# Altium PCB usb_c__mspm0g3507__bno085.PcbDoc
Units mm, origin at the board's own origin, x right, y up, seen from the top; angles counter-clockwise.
Board outline 92 x 60 mm, 2 copper layers (Top, Bottom), stack 0 mm thick; 44 components, 36 nets, 224 pads, 88 vias.
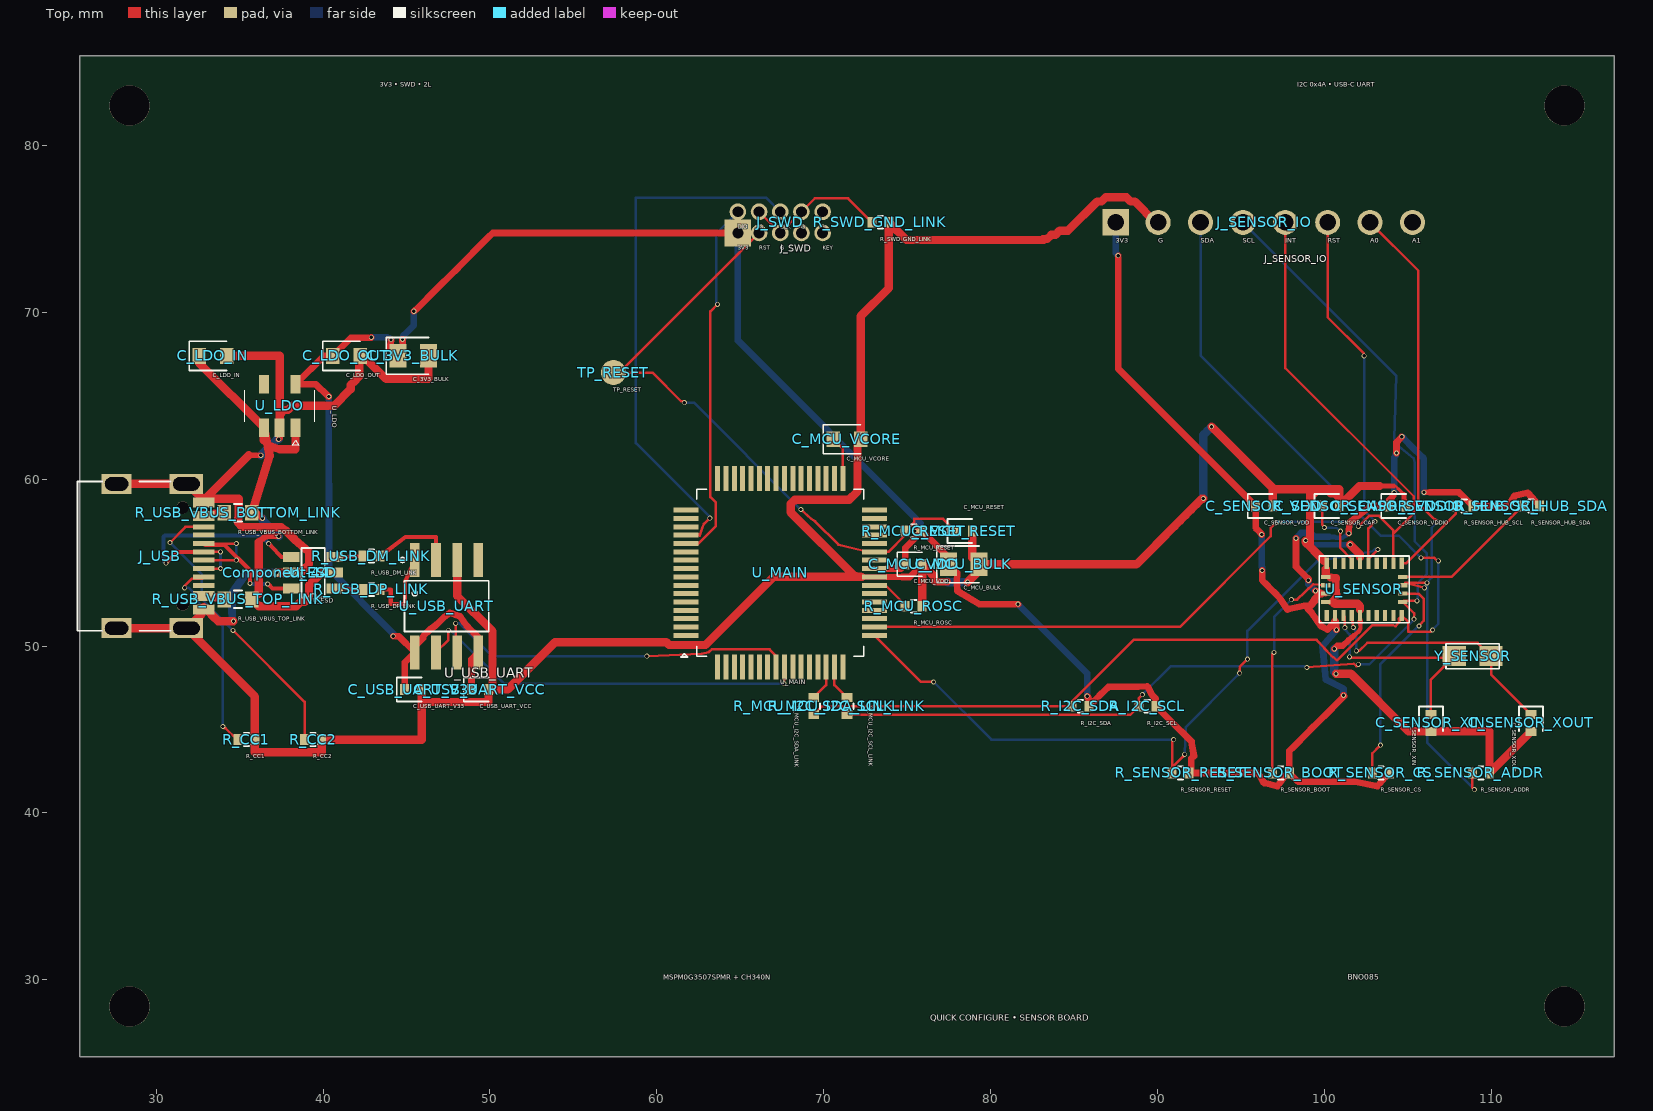
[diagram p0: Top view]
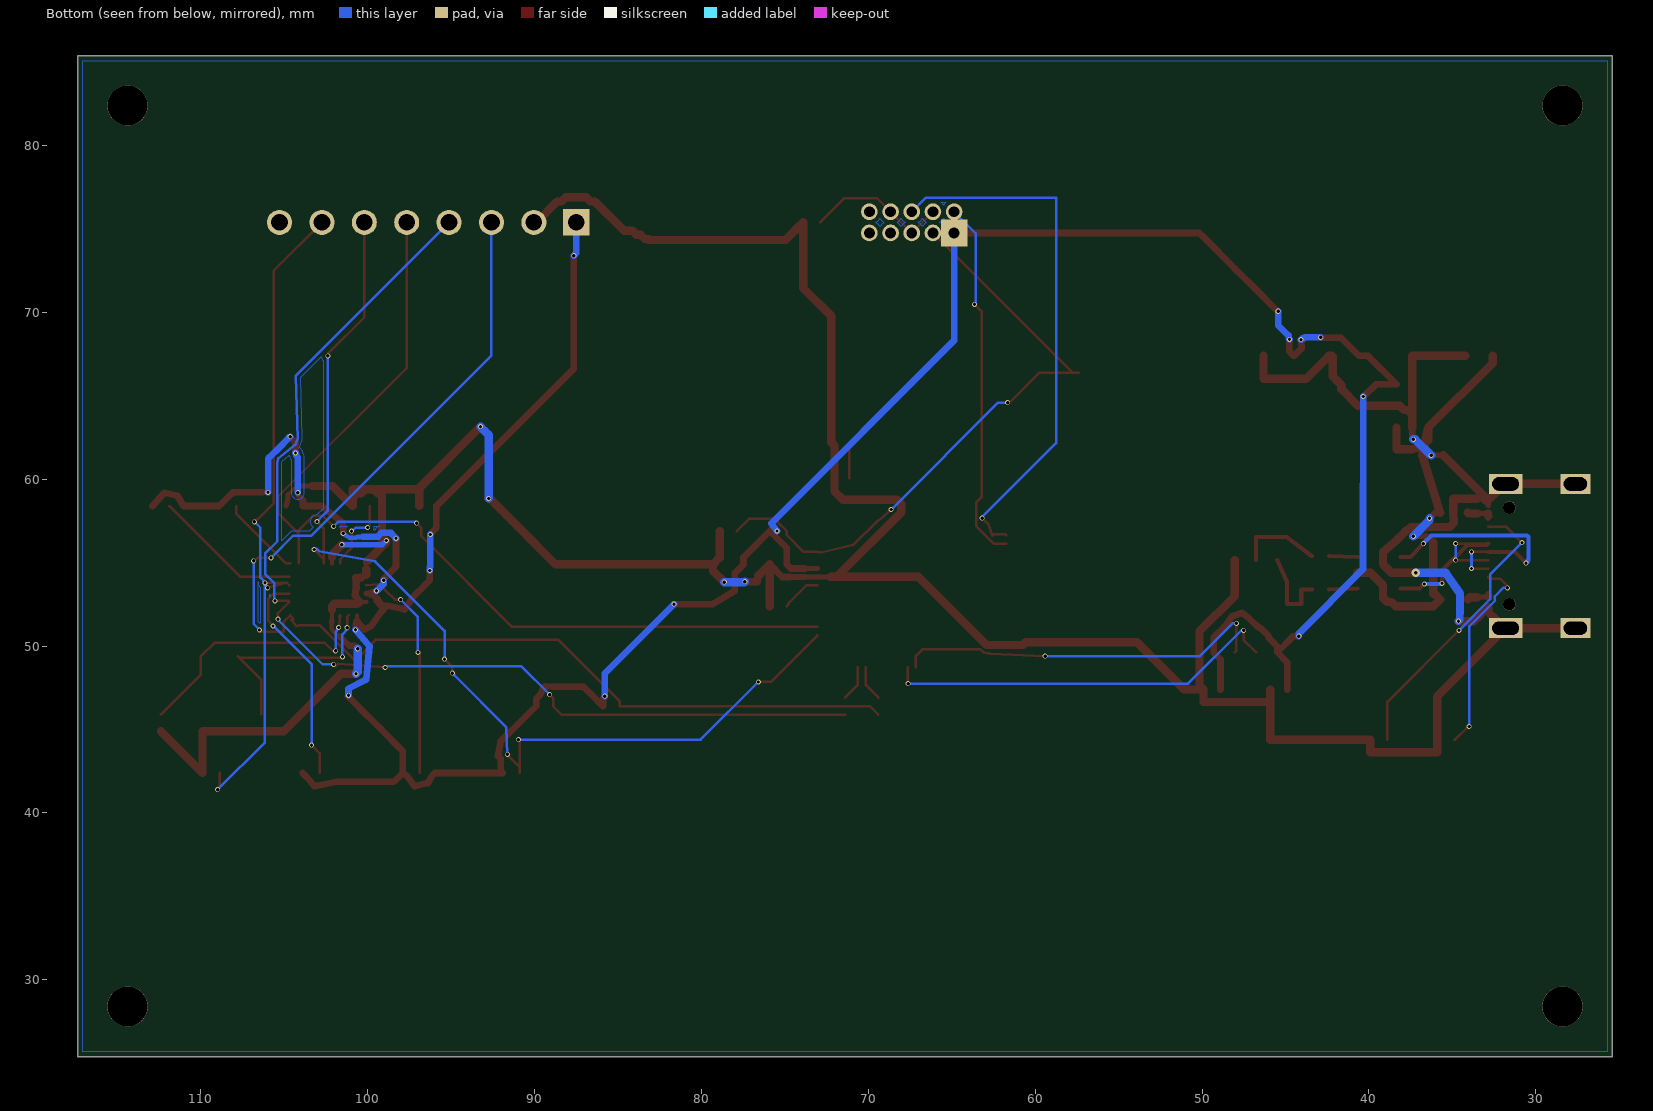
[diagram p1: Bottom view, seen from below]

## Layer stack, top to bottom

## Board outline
25.4,85.4 117.4,85.4 117.4,25.4 25.4,25.4

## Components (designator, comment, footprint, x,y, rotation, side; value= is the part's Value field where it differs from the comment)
C_3V3_BULK "" TSCIRCUIT-2.8500x1.4000mm 45.4,67.4 r0 top
C_LDO_IN "" TSCIRCUIT-2.4500x0.9500mm 33.4,67.4 r0 top
C_LDO_OUT "" TSCIRCUIT-2.4500x0.9500mm 41.4,67.4 r0 top
C_MCU_BULK "" TSCIRCUIT-2.8500x1.4000mm 78.4,54.9 r0 top
C_MCU_RESET "" TSCIRCUIT-1.5600x0.6400mm 78.4,56.9 r0 top
C_MCU_VCORE "" TSCIRCUIT-2.4500x0.9500mm 71.4,62.4 r0 top
C_MCU_VDD "" TSCIRCUIT-1.5600x0.6400mm 75.4,54.9 r0 top
C_SENSOR_CAP "" TSCIRCUIT-1.5600x0.6400mm 100.4,58.4 r0 top
C_SENSOR_VDD "" TSCIRCUIT-1.5600x0.6400mm 96.4,58.4 r0 top
C_SENSOR_VDDIO "" TSCIRCUIT-1.5600x0.6400mm 104.4,58.4 r0 top
C_SENSOR_XIN "" TSCIRCUIT-0.6400x1.5600mm 106.4,45.4 r270 top
C_SENSOR_XOUT "" TSCIRCUIT-0.6400x1.5600mm 112.4,45.4 r270 top
C_USB_UART_V33 "" TSCIRCUIT-1.5600x0.6400mm 45.4,47.4 r0 top
C_USB_UART_VCC "" TSCIRCUIT-1.5600x0.6400mm 49.4,47.4 r0 top
Component-44 "" TSCIRCUIT-0.5000x0.5000mm 37.2,54.4 r0 top
J_SENSOR_IO "" TSCIRCUIT-19.2800x1.5000mm 96.4,75.4 r0 top
J_SWD "" TSCIRCUIT-6.0800x2.2700mm 67.4,75.4 r0 top
J_USB "" TSCIRCUIT-6.7732x9.8502mm 30.113,55.4 r90 top
R_CC1 "" TSCIRCUIT-1.5600x0.6400mm 35.4,44.4 r0 top
R_CC2 "" TSCIRCUIT-1.5600x0.6400mm 39.4,44.4 r0 top
R_I2C_SCL "" TSCIRCUIT-1.5600x0.6400mm 89.4,46.4 r0 top
R_I2C_SDA "" TSCIRCUIT-1.5600x0.6400mm 85.4,46.4 r0 top
R_MCU_I2C_SCL_LINK "" TSCIRCUIT-0.6400x1.5600mm 71.4,46.4 r270 top
R_MCU_I2C_SDA_LINK "" TSCIRCUIT-0.6400x1.5600mm 69.4,46.4 r270 top
R_MCU_RESET "" TSCIRCUIT-1.5600x0.6400mm 75.4,56.9 r0 top
R_MCU_ROSC "" TSCIRCUIT-1.5600x0.6400mm 75.4,52.4 r0 top
R_SENSOR_ADDR "" TSCIRCUIT-1.5600x0.6400mm 109.4,42.4 r0 top
R_SENSOR_BOOT "" TSCIRCUIT-1.5600x0.6400mm 97.4,42.4 r0 top
R_SENSOR_CS "" TSCIRCUIT-1.5600x0.6400mm 103.4,42.4 r0 top
R_SENSOR_HUB_SCL "" TSCIRCUIT-1.5600x0.6400mm 108.4,58.4 r0 top
R_SENSOR_HUB_SDA "" TSCIRCUIT-1.5600x0.6400mm 112.4,58.4 r0 top
R_SENSOR_RESET "" TSCIRCUIT-1.5600x0.6400mm 91.4,42.4 r0 top
R_SWD_GND_LINK "" TSCIRCUIT-1.5600x0.6400mm 73.4,75.4 r0 top
R_USB_DM_LINK "" TSCIRCUIT-1.5600x0.6400mm 42.9,55.4 r0 top
R_USB_DP_LINK "" TSCIRCUIT-1.5600x0.6400mm 42.9,53.4 r0 top
R_USB_VBUS_BOTTOM_LINK "" TSCIRCUIT-2.4500x0.9500mm 34.9,58 r0 top
R_USB_VBUS_TOP_LINK "" TSCIRCUIT-2.4500x0.9500mm 34.9,52.8 r0 top
TP_RESET "" TSCIRCUIT-1.5000x1.5000mm 57.4,66.4 r0 top
U_ESD "" TSCIRCUIT-3.6000x2.5000mm 39.4,54.4 r0 top
U_LDO "" TSCIRCUIT-2.5000x3.7000mm 37.4,64.4 r270 top
U_MAIN "" TSCIRCUIT-12.8000x12.8000mm 67.4,54.4 r0 top
U_SENSOR "" TSCIRCUIT-5.2000x3.8000mm 102.4,53.4 r0 top
U_USB_UART "" TSCIRCUIT-4.3840x7.5712mm 47.4,52.4 r0 top
Y_SENSOR "" TSCIRCUIT-3.6000x1.2000mm 108.9,49.4 r0 top

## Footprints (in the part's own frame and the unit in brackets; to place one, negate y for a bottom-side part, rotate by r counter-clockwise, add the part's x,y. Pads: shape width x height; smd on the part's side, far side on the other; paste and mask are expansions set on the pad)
TSCIRCUIT-0.5000x0.5000mm [mm]
TSCIRCUIT-0.6400x1.5600mm [mm]
  rect 0.54x0.64 smd: 1(-0.51,0) 2(0.51,0)
  silkscreen extent -0.98,-0.72 0.51,0.72
TSCIRCUIT-1.5000x1.5000mm [mm]
  round 1.5 smd: 1(0,0)
TSCIRCUIT-1.5600x0.6400mm [mm]
  rect 0.54x0.64 smd: 1(-0.51,0) 2(0.51,0)
  silkscreen extent -0.98,-0.72 0.51,0.72
TSCIRCUIT-2.4500x0.9500mm [mm]
  rect 0.8x0.95 smd: 1(-0.825,0) 2(0.825,0)
  silkscreen extent -1.42,-0.87 0.82,0.87
TSCIRCUIT-2.5000x3.7000mm [mm]
  rect 1.1x0.6 smd: 1(1.3,0.95) 2(1.3,0) 3(1.3,-0.95) 4(-1.3,-0.95) 5(-1.3,0.95)
  silkscreen extent -0.95,-2.1 2.35,2.1
TSCIRCUIT-2.8500x1.4000mm [mm]
  rect 1.025x1.4 smd: 1(-0.913,0) 2(0.913,0)
  silkscreen extent -1.63,-1.1 0.91,1.1
TSCIRCUIT-3.6000x1.2000mm [mm]
  rect 1.4x1.2 smd: 1(-1.1,0) 2(1.1,0)
  silkscreen extent -1.6,-0.75 1.6,0.75
TSCIRCUIT-3.6000x2.5000mm [mm]
  rect 1x0.6 smd: 1(-1.3,-0.95) 2(-1.3,0) 3(-1.3,0.95) 4(1.3,0.95) 5(1.3,0) 6(1.3,-0.95)
  silkscreen extent -0.7,-1.49 0.7,1.49
TSCIRCUIT-4.3840x7.5712mm [mm]
  rect 0.574x2.036 smd: 1(-1.905,2.768) 2(-0.635,2.768) 3(0.635,2.768) 4(1.905,2.768) 5(1.905,-2.768) 6(0.635,-2.768) 7(-0.635,-2.768) 8(-1.905,-2.768)
  silkscreen extent -2.79,-1.52 2.53,2.92
TSCIRCUIT-5.2000x3.8000mm [mm]
  rect 0.25x0.675 smd: 1(-2.25,-1.562) 6(-2.25,1.563) 7(-1.75,1.563) 8(-1.25,1.563) 9(-0.75,1.563) 10(-0.25,1.563) 11(0.25,1.563) 12(0.75,1.563) 13(1.25,1.563) 14(1.75,1.563) 15(2.25,1.563) 20(2.25,-1.562) 21(1.75,-1.562) 22(1.25,-1.562) 23(0.75,-1.562) 24(0.25,-1.562) 25(-0.25,-1.562) 26(-0.75,-1.562) 27(-1.25,-1.562) 28(-1.75,-1.562)
  rect 0.575x0.25 smd: 2(-2.312,-0.75) 3(-2.312,-0.25) 4(-2.312,0.25) 5(-2.312,0.75) 16(2.312,0.75) 17(2.312,0.25) 18(2.312,-0.25) 19(2.312,-0.75)
  silkscreen extent -2.7,-2 2.7,2
TSCIRCUIT-6.0800x2.2700mm [mm]
  rect 1.6x1.6 hole 0.65: 1(-2.54,-0.635)
  round 1 hole 0.65: 2(-2.54,0.635) 3(-1.27,0.635) 4(0,0.635) 5(1.27,0.635) 6(2.54,0.635) 7(2.54,-0.635) 8(1.27,-0.635) 9(0,-0.635) 10(-1.27,-0.635)
TSCIRCUIT-6.7732x9.8502mm [mm]
  rect 0.3x1.3 smd: 1(-3.35,-2.737) 2(-3.05,-2.737) 3(-2.55,-2.737) 4(-2.25,-2.737) 5(-1.75,-2.737) 6(-1.25,-2.737) 7(-0.75,-2.737) 8(-0.25,-2.737) 9(0.25,-2.737) 10(0.75,-2.737) 11(1.25,-2.737) 12(1.75,-2.737) 13(2.55,-2.737) 14(2.25,-2.737) 15(3.35,-2.737) 16(3.05,-2.737)
  rect 1.2x2 hole 0.8 slot 1.6 at 90 deg: 17(-4.325,-1.693) 18(4.325,-1.693)
  rect 1.2x1.8 hole 0.8 slot 1.4 at 90 deg: 19(4.325,2.487) 20(-4.325,2.487)
  round 0.75 hole 0.75 unplated: NPTH-1(-2.9,-1.468) NPTH-2(2.9,-1.468)
  silkscreen extent -4.47,-0.75 4.47,4.83
TSCIRCUIT-12.8000x12.8000mm [mm]
  rect 1.5x0.3 smd: 1(-5.65,-3.75) 2(-5.65,-3.25) 3(-5.65,-2.75) 4(-5.65,-2.25) 5(-5.65,-1.75) 6(-5.65,-1.25) 7(-5.65,-0.75) 8(-5.65,-0.25) 9(-5.65,0.25) 10(-5.65,0.75) 11(-5.65,1.25) 12(-5.65,1.75) 13(-5.65,2.25) 14(-5.65,2.75) 15(-5.65,3.25) 16(-5.65,3.75) 33(5.65,3.75) 34(5.65,3.25) 35(5.65,2.75) 36(5.65,2.25) 37(5.65,1.75) 38(5.65,1.25) 39(5.65,0.75) 40(5.65,0.25) 41(5.65,-0.25) 42(5.65,-0.75) 43(5.65,-1.25) 44(5.65,-1.75) 45(5.65,-2.25) 46(5.65,-2.75) 47(5.65,-3.25) 48(5.65,-3.75)
  rect 0.3x1.5 smd: 17(-3.75,5.65) 18(-3.25,5.65) 19(-2.75,5.65) 20(-2.25,5.65) 21(-1.75,5.65) 22(-1.25,5.65) 23(-0.75,5.65) 24(-0.25,5.65) 25(0.25,5.65) 26(0.75,5.65) 27(1.25,5.65) 28(1.75,5.65) 29(2.25,5.65) 30(2.75,5.65) 31(3.25,5.65) 32(3.75,5.65) 49(3.75,-5.65) 50(3.25,-5.65) 51(2.75,-5.65) 52(2.25,-5.65) 53(1.75,-5.65) 54(1.25,-5.65) 55(0.75,-5.65) 56(0.25,-5.65) 57(-0.25,-5.65) 58(-0.75,-5.65) 59(-1.25,-5.65) 60(-1.75,-5.65) 61(-2.25,-5.65) 62(-2.75,-5.65) 63(-3.25,-5.65) 64(-3.75,-5.65)
  silkscreen extent -5.95,-5.05 5,5
TSCIRCUIT-19.2800x1.5000mm [mm]
  rect 1.6x1.6 hole 1: 1(-8.89,0)
  round 1.5 hole 1: 2(-6.35,0) 3(-3.81,0) 4(-1.27,0) 5(1.27,0) 6(3.81,0) 7(6.35,0) 8(8.89,0)

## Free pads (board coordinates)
  round 2.4 hole 2.4 unplated: NPTH-3(28.4,28.4) NPTH-4(114.4,28.4) NPTH-5(28.4,82.4) NPTH-6(114.4,82.4)

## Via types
v1: diameter 0.3, hole 0.2, Top to Bottom, 87 vias
v2: diameter 0.5, hole 0.2, Top to Bottom, 1 vias

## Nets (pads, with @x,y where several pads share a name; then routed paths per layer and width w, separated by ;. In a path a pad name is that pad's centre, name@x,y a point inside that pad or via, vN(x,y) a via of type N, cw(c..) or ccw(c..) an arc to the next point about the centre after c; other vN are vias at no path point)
".J_SWD > .pin2 to .U_MAIN > .pin12": J_SWD.2 U_MAIN.12 | length 21.9
  Top w0.15: U_MAIN.12 62.497,56.15 63.541,57.194 63.541,58.602 63.209,58.934 63.209,70.059 v1(63.641,70.491)
  Bottom w0.15: v1(63.641,70.491) 63.572,70.56 63.572,70.569 63.572,74.747 J_SWD.2
".J_SWD > .pin4 to .U_MAIN > .pin13": J_SWD.4 U_MAIN.13 | length 32.2
  Top w0.15: U_MAIN.13 61.82,56.72 62.513,56.72 62.568,56.628 62.763,57.17 62.829,57.322 63.178,57.671 v1(63.183,57.671)
  Bottom w0.15: v1(63.183,57.671) 63.212,57.7 58.746,62.167 58.746,76.869 66.566,76.869 J_SWD.4
".U_MAIN > .pin42 to .R_MCU_ROSC > .pin1": R_MCU_ROSC.1 U_MAIN.42 | length 2.4
  Top w0.15: U_MAIN.42 73.719,53.65 74.769,52.6 74.769,52.521 R_MCU_ROSC.1
".U_SENSOR > .CAP to .C_SENSOR_CAP > .pin1": C_SENSOR_CAP.1 U_SENSOR.9 | length 4.6
  Top w0.15: C_SENSOR_CAP.1 99.89,57.265 99.972,57.184 99.972,57.142 v1(100.006,57.108) ; v1(100.979,56.887) 100.953,55.907 101.65,55.21 U_SENSOR.9
  Bottom w0.15: v1(100.006,57.108) 100.739,57.098 100.933,56.903 100.941,56.903 v1(100.979,56.887)
".U_SENSOR > .SENSOR_HUB_SCL to .R_SENSOR_HUB_SCL > .pin1": R_SENSOR_HUB_SCL.1 U_SENSOR.15 | length 4.9
  Top w0.15: U_SENSOR.15 104.899,54.962 107.89,57.953 R_SENSOR_HUB_SCL.1
".U_SENSOR > .SENSOR_HUB_SDA to .R_SENSOR_HUB_SDA > .pin1": R_SENSOR_HUB_SDA.1 U_SENSOR.16 | length 8.9
  Top w0.15: U_SENSOR.16 107.64,54.15 R_SENSOR_HUB_SDA.1
GND: C_3V3_BULK.2 C_LDO_IN.2 C_LDO_OUT.2 C_MCU_BULK.2 C_MCU_RESET.2 C_MCU_VCORE.2 C_MCU_VDD.2 C_SENSOR_CAP.2 C_SENSOR_VDD.2 C_SENSOR_VDDIO.2 C_SENSOR_XIN.2 C_SENSOR_XOUT.2 C_USB_UART_V33.2 C_USB_UART_VCC.2 J_SENSOR_IO.2 J_USB.1 J_USB.2 J_USB.15 J_USB.16 J_USB.17 J_USB.18 J_USB.19 J_USB.20 R_CC1.2 R_CC2.2 R_MCU_ROSC.2 R_SENSOR_ADDR.2 R_SWD_GND_LINK.2 U_ESD.2 U_LDO.2 U_MAIN.41 U_SENSOR.2 U_SENSOR.5 U_SENSOR.6 U_SENSOR.10 U_SENSOR.25 U_USB_UART.3 | length 259
  Top w0.188: 104.163,59.6 104.279,59.601 104.539,59.35
  Top w0.2: 104.539,59.35 104.782,59.108
  Top w0.25: U_SENSOR.5@100.088,54.275 U_SENSOR.5 U_SENSOR.5@100.375,54.121 ; U_SENSOR.6@100.088,54.625 100.088,54.9 U_SENSOR.6 ; U_SENSOR.2@100.369,52.65 U_SENSOR.2 U_SENSOR.2@100.375,52.618 ; 101.775,50.63 102.087,50.9 102.168,51.048 102.159,51.443 ; U_SENSOR.25@102.15,52.175 U_SENSOR.25 102.158,51.5 ; U_SENSOR.10 102.15,55.056 102.15,55.15 102.15,55.244 102.15,55.3 102.15,55.337 ; U_SENSOR.6 100.025,55.087 U_SENSOR.6
  Top w0.275: J_USB.2 J_USB.1@33.132,52.067 ; J_USB.16 J_USB.15@33.04,58.641 ; 104.782,59.097 104.782,59.108
  Top w0.3: J_USB.1@32.699,51.9 J_USB.1 J_USB.1@32.849,52.2 ; J_USB.15@32.699,58.9 J_USB.15 ; J_USB.16@32.849,58.6 J_USB.15 ; J_USB.15@32.999,58.9 J_USB.15 ; J_USB.15@33.04,58.641 33.231,58.832 33.499,58.832 ; U_MAIN.41@73.8,54.15 73.706,54.15 73.612,54.15 73.519,54.15 73.425,54.15 73.331,54.15 73.237,54.15 73.144,54.15 U_MAIN.41 ; 103.342,59.6 103.752,59.6 104.163,59.6 ; U_MAIN.41 72.627,54.15 72.3,54.15 72.585,54.15 U_MAIN.41
  Top w0.312: U_SENSOR.2@100.369,52.65 100.775,53.056 ; 104.782,59.097 104.782,58.813 C_SENSOR_VDDIO.2
  Top w0.325: J_USB.16 J_USB.16@32.849,58.6 ; 35.535,61.436 35.899,61.436 v1(36.263,61.436) ; U_SENSOR.2@100.375,52.618 100.572,52.595 ; 101.462,50.361 101.775,50.63 ; 102.158,51.5 102.159,51.443
  Top w0.35: v1(37.334,62.399) v1@37.4,62.465
  Top w0.375: U_MAIN.41@73.8,54.15 74.253,54.15 74.707,54.15 ; v1(100.611,49.837) 100.791,50.017 ; 101.108,50.017 101.462,50.361
  Top w0.4: 37.2,54.4 U_ESD.2@37.6,54.4 ; v1@37.4,62.465 37.4,62.6 U_LDO.2 ; 74.707,54.15 75.16,54.15 75.41,54.4 75.66,54.65 C_MCU_VDD.2 ; 100.791,50.017 101.108,50.017
  Top w0.437: 100.705,53.806 100.697,53.525 100.775,53.056
  Top w0.45: 76.599,54.211 76.65,53.869 77.025,53.868 v1(77.4,53.867) ; 100.705,53.806 100.713,54.087
  Top w0.475: 71.655,54.15 72.12,54.15 72.3,54.15 72.205,54.15 ; U_SENSOR.5@100.375,54.121 100.4,54.119 100.713,54.087
  Top w0.5: J_USB.20 J_USB.17 ; J_USB.19 J_USB.18 31.874,59.725 32.474,59.125 32.699,58.9 ; 32.699,51.9 32.474,51.675 31.874,51.075 J_USB.17 ; J_USB.1@32.849,52.2 J_USB.2 ; 32.999,58.9 35.535,61.436 ; J_USB.1@33.132,52.067 33.416,51.783 33.699,51.5 v1(34.631,51.5) ; 33.499,58.832 33.658,58.832 34.086,58.832 34.513,58.832 34.941,58.832 34.939,58.436 34.936,58.041 34.9,57.4 35.15,57.15 35.619,57.144 36.087,57.138 36.556,57.131 37.025,57.125 37.494,57.119 37.73,56.959 38.02,56.669 38.311,56.378 39.15,55.65 39.15,54.9 38.9,54.65 38.65,54.4 37.2,54.4 ; C_LDO_IN.2 37.4,67.4 U_LDO.2 37.4,63.9 37.65,64.15 37.9,64.15 38.15,64.4 40.65,64.4 41.65,65.4 41.65,65.65 41.9,65.9 41.9,65.897 41.839,65.836 42.163,66.176 42.163,66.563 42.163,66.951 42.163,67.338 C_LDO_OUT.2 42.4,67.4 43.775,66.025 46.313,66.025 C_3V3_BULK.2 ; U_USB_UART.3 48.035,53.015 50.15,50.9 50.15,47.65 49.91,47.41 C_USB_UART_VCC.2 ; 71.655,54.15 71.19,54.15 70.725,54.15 70.26,54.15 69.796,54.15 69.331,54.15 68.866,54.15 68.401,54.15 67.936,54.15 67.471,54.15 67.006,54.15 62.923,50.067 60.733,50.067 60.567,50.233 53.9,50.233 51.067,47.4 C_USB_UART_VCC.2 ; 72.205,54.15 71.994,54.15 71.947,54.197 71.853,54.197 68.025,58.025 68.025,58.525 68.275,58.775 71.525,58.775 72.025,59.275 72.025,62.025 72.225,62.225 C_MCU_VCORE.2 72.225,62.892 72.225,63.384 72.225,63.876 72.225,64.368 72.225,64.86 72.225,65.352 72.225,65.844 72.225,66.336 72.225,66.828 72.225,67.32 72.225,67.812 72.225,68.303 72.225,68.795 72.225,69.287 72.225,69.779 73.91,71.464 R_SWD_GND_LINK.2 74.262,75.048 74.613,74.697 74.965,74.345 74.987,74.345 75.47,74.345 75.953,74.345 76.436,74.345 76.919,74.345 77.402,74.345 77.885,74.345 78.368,74.345 78.851,74.345 79.335,74.345 79.818,74.345 80.301,74.345 80.784,74.345 81.267,74.345 81.75,74.345 82.233,74.345 82.716,74.345 83.199,74.345 83.15,74.394 83.15,74.4 83.4,74.4 83.65,74.65 83.9,74.65 84.15,74.9 84.65,74.9 86.4,76.65 86.65,76.65 86.9,76.9 88.15,76.9 88.4,76.65 88.65,76.65 89.9,75.4 J_SENSOR_IO.2 ; R_MCU_ROSC.2 C_MCU_VDD.2 76.254,54.556 76.599,54.211 ; v1(78.637,53.838) 79.313,54.513 C_MCU_BULK.2 ; C_MCU_RESET.2 78.91,55.303 C_MCU_BULK.2 ; v1(92.753,58.848) 92.742,58.837 92.681,58.837 92.353,58.509 92.025,58.181 91.697,57.853 91.369,57.525 91.041,57.197 90.713,56.869 90.385,56.541 90.056,56.212 89.728,55.884 89.4,55.556 89.072,55.228 88.744,54.9 88.248,54.9 87.751,54.9 87.255,54.9 86.758,54.9 86.262,54.9 85.766,54.9 85.269,54.9 84.773,54.9 84.276,54.9 83.78,54.9 83.284,54.9 82.787,54.9 82.291,54.9 81.794,54.9 81.298,54.9 80.802,54.9 80.305,54.9 79.809,54.9 C_MCU_BULK.2 ; v1(93.25,63.155) 96.91,59.495 C_SENSOR_VDD.2 96.91,59.4 100.91,59.4 C_SENSOR_CAP.2 ; v1(98.893,56.332) 98.893,56.219 99.207,55.905 99.522,55.591 99.836,55.277 100.025,55.087 99.15,55.962 99.15,59.15 99.4,59.15 99.65,59.4 100.15,59.4 100.4,59.15 100.65,59.15 100.9,58.9 100.9,58.65 100.91,58.64 C_SENSOR_CAP.2 ; 100.088,54.275 100.088,54.625 ; 100.572,52.595 100.627,52.541 101.056,52.541 102.009,52.541 102.15,52.4 U_SENSOR.25@102.15,52.175 ; v1(100.705,48.345) 101.153,48.345 101.601,48.345 105.056,44.89 C_SENSOR_XIN.2 109.91,44.89 R_SENSOR_ADDR.2 110.087,42.577 C_SENSOR_XOUT.2 ; v1(101.559,56.081) v1@101.639,56.001 ; v1@101.639,56 101.992,55.647 102.058,55.581 102.125,55.514 102.15,55.489 102.15,55.431 102.15,55.337 ; 103.342,59.6 102.931,59.6 102.521,59.6 102.11,59.6 101.81,59.3 101.51,59 101.21,58.7 C_SENSOR_CAP.2 ; J_USB.17 35.91,46.971 R_CC1.2 35.91,43.65 39.91,43.65 R_CC2.2 40.41,44.4 40.91,44.4 45.91,44.4 C_USB_UART_V33.2 45.91,46.65 49.91,46.65 C_USB_UART_VCC.2
  Bottom w0.325: v1(98.893,56.332) 98.909,56.316 99.144,56.081 99.627,56.081 100.11,56.081 100.593,56.081
  Bottom w0.337: 100.593,56.081 101.076,56.081
  Bottom w0.35: 101.076,56.081 v1(101.559,56.081)
  Bottom w0.45: 34.543,51.978 34.543,51.588 v1(34.631,51.5)
  Bottom w0.5: 34.543,51.978 34.543,52.368 34.543,52.759 34.543,53.149 35.4,54.4 36.263,54.4 36.731,54.4 37.2,54.4 ; v1(36.263,61.436) 37.226,62.399 v1(37.334,62.399) ; v1(77.4,53.867) 77.429,53.838 v1(78.637,53.838) ; v1(92.753,58.848) 92.753,59.324 92.753,59.801 92.753,60.277 92.753,60.753 92.753,61.229 92.753,61.706 92.753,62.182 92.753,62.658 92.996,62.901 93.24,63.145 v1(93.25,63.155) ; v1(100.611,49.837) 100.611,49.374 100.611,48.911 100.611,48.448 100.689,48.371 100.689,48.361 v1(100.705,48.345)
MAIN_RESET: C_MCU_RESET.1 J_SWD.10 R_MCU_RESET.1 TP_RESET.1 U_MAIN.38 | length 38.4
  Top w0.15: v1(61.65,64.593) 61.562,64.681 61.452,64.681 59.733,66.4 TP_RESET.1 57.765,66.4 J_SWD.10 ; v1(68.634,58.195) 69.254,57.626 69.493,57.483 70.886,56.087 72.817,55.614 73.014,55.614 U_MAIN.38 73.889,55.65 74.889,56.651 R_MCU_RESET.1@74.889,56.899 ; R_MCU_RESET.1 75.442,57.452 75.442,57.636 77.166,57.628 C_MCU_RESET.1
  Bottom w0.15: v1(61.65,64.593) 62.221,64.593 68.534,58.28 68.541,58.28 v1(68.634,58.195)
MCU_I2C_SCL_LOCAL: R_MCU_I2C_SCL_LINK.1 U_MAIN.50 | length 2.2
  Top w0.15: U_MAIN.50 70.65,47.66 R_MCU_I2C_SCL_LINK.1
MCU_I2C_SDA_LOCAL: R_MCU_I2C_SDA_LINK.1 U_MAIN.51 | length 2.2
  Top w0.15: R_MCU_I2C_SDA_LINK.1 70.15,47.66 U_MAIN.51
MSPM0_VCORE: C_MCU_VCORE.1 U_MAIN.32 | length 2.6
  Top w0.15: C_MCU_VCORE.1 71.15,61.825 U_MAIN.32
SENSOR_ADDR0: J_SENSOR_IO.7 R_SENSOR_ADDR.1 U_SENSOR.17 | length 41.4
  Top w0.15: J_SENSOR_IO.7 105.651,72.499 105.645,58.602 105.651,58.558 106.614,57.595 106.661,57.595 v1(106.8,57.456) ; v1(106,53.5) 104.861,53.798 ; v1(106.164,53.798) 104.861,53.798 ; R_SENSOR_ADDR.1 108.89,41.517 108.973,41.434 108.973,41.427 v1(109,41.4) ; 104.861,53.798 U_SENSOR.17 104.861,53.798
  Bottom w0.15: v1(106,53.5) 106.171,53.792 106.168,53.571 106.169,44.229 v1(109,41.4) ; v1(106.164,53.798) 106.264,53.899 106.264,53.931 106.44,54.107 106.44,57.096 v1(106.8,57.456)
SENSOR_ADDR1: J_SENSOR_IO.8
SENSOR_BOOT: R_SENSOR_BOOT.1 U_SENSOR.4 | length 13.3
  Top w0.15: R_SENSOR_BOOT.1 96.89,49.521 96.968,49.599 v1(96.997,49.628) ; v1(98.031,52.785) 98.376,52.785 99.356,53.713 U_SENSOR.4
  Bottom w0.15: v1(96.997,49.628) 96.997,51.751 97.969,52.723 v1(98.031,52.785)
SENSOR_CS: R_SENSOR_CS.1 U_SENSOR.18 | length 13.1
  Top w0.15: R_SENSOR_CS.1 102.89,43.58 103.293,43.983 103.296,43.983 v1(103.374,44.061) ; U_SENSOR.18 105.665,53.15 105.962,52.853 105.962,51.518 v1(105.686,51.206)
  Bottom w0.15: v1(103.374,44.061) 103.374,48.918 105.591,51.136 105.591,51.147 v1(105.686,51.206)
SENSOR_INT: J_SENSOR_IO.5 U_MAIN.47 U_SENSOR.14 | length 60.9
  Top w0.15: U_MAIN.47 91.356,51.15 96.796,56.59 96.796,57.092 96.971,57.267 ; 96.972,57.267 v1(97.078,57.373) ; J_SENSOR_IO.5 97.67,66.671 105.37,58.986 105.37,57.945 104.996,57.586 104.15,56.74 U_SENSOR.14 104.15,56.944 103.291,57.803 102.675,57.803 v1(102.053,57.179)
  Bottom w0.15: v1(97.078,57.373) 97.17,57.465 101.537,57.465 101.767,57.465 v1(102.053,57.179)
SENSOR_RESET: J_SENSOR_IO.6 R_SENSOR_RESET.1 U_MAIN.48 U_SENSOR.11 | length 65.4
  Top w0.15: U_MAIN.48 75.848,47.852 v1(76.597,47.852) ; v1(90.98,44.4) 90.98,44.362 90.89,44.272 R_SENSOR_RESET.1 90.89,42.72 91.548,43.378 v1(91.64,43.52) ; v1(94.931,48.384) 94.931,48.748 95.378,49.195 v1(95.404,49.221) ; J_SENSOR_IO.6 100.21,69.715 102.377,67.548 102.377,67.417 v1(102.397,67.397) ; v1(103.049,57.461) 102.65,57.062 U_SENSOR.11 102.65,55.229 v1(103.216,55.795)
  Bottom w0.15: v1(76.597,47.852) 76.643,47.806 80.049,44.4 v1(90.98,44.4) ; v1(91.64,43.52) 91.69,45.135 94.79,48.235 94.79,48.243 v1(94.931,48.384) ; v1(95.404,49.221) 95.404,50.917 99.563,55.076 102.917,55.7 103.065,55.848 103.163,55.848 v1(103.216,55.795) ; v1(102.397,67.397) 102.397,58.125 102.911,57.611 102.911,57.599 v1(103.049,57.461)
SENSOR_SCL: J_SENSOR_IO.4 R_I2C_SCL.1 R_MCU_I2C_SCL_LINK.2 U_SENSOR.19 | length 66.5
  Top w0.15: R_MCU_I2C_SCL_LINK.2 88.38,45.89 R_I2C_SCL.1 88.89,46.887 89.075,47.072 v1(89.098,47.096) ; v1(98.959,48.722) 101.775,48.948 101.922,48.807 101.945,48.807 v1(102.053,48.915) ; v1(105.384,51.622) 105.4,51.962 U_SENSOR.19 104.779,52.716 v1(105.566,52.716)
  Bottom w0.15: v1(89.098,47.096) 90.808,48.805 98.876,48.805 v1(98.959,48.722) ; J_SENSOR_IO.4 104.312,66.218 104.205,62.442 104.312,62.112 105.375,61.25 105.432,60.992 105.432,56.277 106.162,55.546 106.162,54.331 105.609,53.777 105.609,52.779 105.609,52.759 v1(105.566,52.716) ; v1(102.053,48.915) 102.715,48.915 105.291,51.491 v1(105.384,51.622)
SENSOR_SDA: J_SENSOR_IO.3 R_I2C_SDA.1 R_MCU_I2C_SDA_LINK.2 U_SENSOR.20 | length 73.5
  Top w0.15: R_MCU_I2C_SDA_LINK.2 69.91,46.4 R_I2C_SDA.1 84.89,46.689 88.575,50.374 99.545,50.374 100.425,49.438 100.774,49.145 102.888,51.259 104.146,51.259 104.264,51.183 104.581,51.577 104.465,51.597 104.465,51.645 U_SENSOR.20 105.051,51.436 105.051,50.865 106.399,50.866 v1(106.508,50.972) ; v1(105.801,55.289) 106.603,55.289 106.742,55.15 106.814,55.15 v1(106.847,55.117)
  Bottom w0.15: J_SENSOR_IO.3 92.59,67.422 103.389,56.623 104.47,56.623 105.756,55.337 105.756,55.334 v1(105.801,55.289) ; v1(106.508,50.972) 106.516,50.984 106.516,51.011 106.847,51.342 v1(106.847,55.117)
SENSOR_XIN: C_SENSOR_XIN.1 U_SENSOR.27 Y_SENSOR.1 | length 13
  Top w0.15: U_SENSOR.27 101.226,51.761 v1(101.237,51.107) ; v1(101.52,49.355) 101.558,49.317 101.585,49.317 107.717,49.317 Y_SENSOR.1 106.4,48 C_SENSOR_XIN.1
  Bottom w0.15: v1(101.237,51.107) 101.243,51.071 101.243,50.987 101.52,50.71 v1(101.52,49.355)
SENSOR_XOUT: C_SENSOR_XOUT.1 U_SENSOR.26 Y_SENSOR.2 | length 15.4
  Top w0.15: U_SENSOR.26 101.705,51.782 101.662,51.8 v1(101.752,51.117) ; v1(101.931,49.716) 101.933,49.714 102.098,49.714 102.583,50.199 102.647,50.199 109.201,50.199 Y_SENSOR.2 110,48.31 C_SENSOR_XOUT.1
  Bottom w0.15: v1(101.752,51.117) 101.859,50.94 101.859,50.935 101.931,50.863 v1(101.931,49.716)
swd-ground-1-to-2: J_SWD.3 J_SWD.5 J_SWD.9 R_SWD_GND_LINK.1 | length 8.8
  Top w0.15: J_SWD.3 J_SWD.9 J_SWD.5 69.481,76.846 71.471,76.846 71.471,76.819 R_SWD_GND_LINK.1
UART_MSP_RX: U_MAIN.57 U_USB_UART.6 | length 22.7
  Top w0.15: v1(47.946,51.37) 47.946,49.721 U_USB_UART.6 ; v1(59.4,49.4) 59.432,49.4 62.701,49.544 63.1,49.635 63.3,49.801 66.767,49.802 67.151,49.417 U_MAIN.57
  Bottom w0.15: v1(47.946,51.37) 47.952,51.376 48.148,51.376 50.124,49.4 v1(59.4,49.4)
UART_MSP_TX: U_MAIN.56 U_USB_UART.7 | length 24.1
  Top w0.15: U_USB_UART.7 47.507,50.374 v1(47.507,50.948) ; v1(67.611,47.75) 67.621,47.76 67.621,47.762 67.65,47.792 U_MAIN.56
  Bottom w0.15: v1(47.507,50.948) 47.526,50.967 47.621,50.967 50.839,47.75 v1(67.611,47.75)
usb-dm-device: R_USB_DM_LINK.1 U_ESD.4 | length 1.7
  Top w0.25: U_ESD.4 R_USB_DM_LINK.1
usb-dm-port-tie: J_USB.7 J_USB.9 U_ESD.3 | length 15.4
  Top w0.15: J_USB.7 v1(33.85,54.65) ; J_USB.9 v1(33.85,55.65)
  Top w0.25: v1(30.582,54.978) 31.254,55.65 J_USB.9 ; v1(36.741,56.142) 36.868,56.015 36.868,55.996 37.514,55.35 U_ESD.3
  Bottom w0.15: v1(33.85,54.65) v1(33.85,55.65)
  Bottom w0.25: v1(30.582,54.978) 30.477,55.083 30.477,55.132 30.444,55.165 30.438,55.368 30.429,56.554 30.514,56.624 36.259,56.624 v1(36.741,56.142)
usb-dm-uart: R_USB_DM_LINK.2 U_USB_UART.2 | length 5.1
  Top w0.25: R_USB_DM_LINK.2 44.95,56.55 46.765,56.55 U_USB_UART.2
usb-dp-device: R_USB_DP_LINK.1 U_ESD.6 | length 1.7
  Top w0.25: U_ESD.6 R_USB_DP_LINK.1
usb-dp-port-tie: J_USB.8 J_USB.10 U_ESD.1 | length 11.7
  Top w0.15: J_USB.8 v1(34.8,55.15) ; J_USB.10 v1(34.8,56.15)
  Top w0.25: J_USB.10 32.931,56.068 34.097,56.068 35.631,54.534 v1(35.621,53.765) ; v1(36.679,53.724) 36.687,53.716 36.71,53.716 36.976,53.45 U_ESD.1
  Bottom w0.15: v1(34.8,55.15) v1(34.8,56.15)
  Bottom w0.25: v1(35.621,53.765) 35.665,53.742 35.688,53.742 35.706,53.724 v1(36.679,53.724)
usb-dp-uart: R_USB_DP_LINK.2 U_USB_UART.1 | length 5.1
  Top w0.25: R_USB_DP_LINK.2 44.05,53.4 44.05,52.53 44.9,52.53 44.9,53.85 U_USB_UART.1
USB_CC1: J_USB.6 R_CC1.1 | length 12.1
  Top w0.15: v1(31.698,53.499) 31.698,53.616 32.135,54.053 32.752,54.053 J_USB.6 ; v1(33.986,45.184) 34.102,45.068 34.167,45.068 34.835,44.4 R_CC1.1
  Bottom w0.15: v1(31.698,53.499) 31.704,53.505 31.935,53.505 32.45,52.991 32.45,52.722 33.986,51.186 v1(33.986,45.184)
USB_CC2: J_USB.12 R_CC2.1 | length 17.6
  Top w0.15: v1(30.822,56.2) 31.75,57.15 J_USB.12 ; v1(34.603,50.946) 34.657,50.892 38.89,46.659 R_CC2.1
  Bottom w0.15: v1(30.822,56.2) 30.847,56.153 30.885,56.153 32.739,54.3 32.739,54.172 32.739,52.81 v1(34.603,50.946)
USB_VBUS_BOTTOM_LOCAL: J_USB.13 J_USB.14 R_USB_VBUS_BOTTOM_LINK.1 | length 1.5
  Top w0.3: J_USB.14 J_USB.14@32.849,57.8 ; J_USB.13 32.927,57.95 33.005,57.95 33.083,57.95 33.161,57.95 33.239,57.95 33.317,57.95 33.394,57.95 33.472,57.95 33.499,57.95
  Top w0.475: J_USB.13@32.849,57.8 J_USB.13 ; 33.499,57.95 R_USB_VBUS_BOTTOM_LINK.1@33.762,57.95
  Top w0.5: R_USB_VBUS_BOTTOM_LINK.1@33.762,57.95 34.025,57.95 R_USB_VBUS_BOTTOM_LINK.1
USB_VBUS_TOP_LOCAL: J_USB.3 J_USB.4 R_USB_VBUS_TOP_LINK.1 | length 1.6
  Top w0.3: J_USB.4 32.849,53 J_USB.3 32.944,52.958 33.032,52.939 33.499,52.939
  Top w0.5: 33.499,52.939 33.675,52.939 33.936,52.939 R_USB_VBUS_TOP_LINK.1
VBUS5: C_LDO_IN.1 R_USB_VBUS_BOTTOM_LINK.2 R_USB_VBUS_TOP_LINK.2 U_ESD.5 U_LDO.1 U_LDO.3 | length 29.2
  Top w0.325: v1@36.341,57.68 v1(36.364,57.657)
  Top w0.35: 36.582,56.587 36.958,56.587 v1(37.333,56.587)
  Top w0.375: R_USB_VBUS_BOTTOM_LINK.2 36.021,58 v1@36.341,57.68 ; 36.15,56.246 36.272,56.369 36.582,56.587
  Top w0.5: C_LDO_IN.1 32.575,66.975 U_LDO.3 ; R_USB_VBUS_BOTTOM_LINK.2 36.8,61.4 U_LDO.3 ; 36.15,56.246 36.15,53.15 36.075,53.15 R_USB_VBUS_TOP_LINK.2 35.981,52.544 35.9,52.625 35.9,52.65 36.15,52.4 38.4,52.4 38.65,52.65 38.9,52.65 39.15,52.9 39.15,53.65 39.9,54.4 U_ESD.5 ; U_LDO.1 38.35,61.8 37.4,61.8 36.8,62 36.45,62.35 U_LDO.3
  Bottom w0.5: v1(36.364,57.657) 36.364,57.556 v1(37.333,56.587)
VCC_3V3: C_3V3_BULK.1 C_LDO_OUT.1 C_MCU_BULK.1 C_MCU_VDD.1 C_SENSOR_VDD.1 C_SENSOR_VDDIO.1 C_USB_UART_V33.1 C_USB_UART_VCC.1 J_SENSOR_IO.1 J_SWD.1 R_I2C_SCL.2 R_I2C_SDA.2 R_MCU_RESET.2 R_SENSOR_BOOT.2 R_SENSOR_CS.2 R_SENSOR_HUB_SCL.2 R_SENSOR_HUB_SDA.2 R_SENSOR_RESET.2 U_LDO.5 U_MAIN.40 U_SENSOR.3 U_SENSOR.28 U_USB_UART.5 U_USB_UART.8 | length 205.1
  Top w0.25: U_SENSOR.3@99.851,53.124 100.062,53.124 U_SENSOR.3 ; 100.611,51.5 U_SENSOR.28 100.685,51.5
  Top w0.3: U_MAIN.40 73.15,54.65 73.25,54.65 73.35,54.65 73.45,54.65 73.55,54.65 73.65,54.65 73.75,54.65 U_MAIN.40@73.8,54.65 ; 104.187,59.027 104.187,59.187 v1(104.199,59.199)
  Top w0.325: 104.038,58.879 104.187,59.027 ; v1(105.985,59.219) 106.336,59.219
  Top w0.345: U_SENSOR.3@99.8,53.2 U_SENSOR.3 U_SENSOR.3@99.8,53.2
  Top w0.4: v1(40.348,64.966) 40.311,64.974 40.292,64.983 39.552,65.7 U_LDO.5 40.05,67.4 C_LDO_OUT.1 41.663,68.488 42.876,68.5 v1(42.889,68.512) ; v1(44.072,68.366) 44.017,67.871 C_3V3_BULK.1 44.634,67.546 44.781,67.693 44.768,68.039 v1(44.755,68.386) ; v1(44.2,50.6) 44.527,50.6 U_USB_UART.8 ; C_USB_UART_V33.1 44.89,49.027 U_USB_UART.8 ; v1(45.438,70.073) 45.494,70.129 45.53,70.129 45.803,70.402 46.076,70.675 46.348,70.947 46.621,71.22 46.894,71.493 47.166,71.765 47.439,72.038 47.712,72.311 47.984,72.584 48.257,72.856 48.53,73.129 48.802,73.402 49.075,73.674 49.348,73.947 49.621,74.22 49.893,74.492 50.166,74.765 50.563,74.765 50.96,74.765 51.357,74.765 51.754,74.765 52.152,74.765 52.549,74.765 52.946,74.765 53.343,74.765 53.74,74.765 54.137,74.765 54.534,74.765 54.932,74.765 55.329,74.765 55.726,74.765 56.123,74.765 56.52,74.765 56.917,74.765 57.314,74.765 57.712,74.765 58.109,74.765 58.506,74.765 58.903,74.765 59.3,74.765 59.697,74.765 60.094,74.765 60.491,74.765 60.889,74.765 61.286,74.765 61.683,74.765 62.08,74.765 62.477,74.765 62.874,74.765 63.271,74.765 63.669,74.765 64.066,74.765 64.463,74.765 J_SWD.1 ; C_USB_UART_VCC.1 48.89,49.217 U_USB_UART.5 49.305,49.93 49.305,50.228 49.305,50.526 49.078,50.753 48.851,50.98 48.623,51.207 48.2,51.8 47.6,52 47.242,51.735 46.992,51.486 46.743,51.236 46.4,51 46,50.6 45.994,50.488 45.745,50.238 45.495,49.989 U_USB_UART.8 ; U_MAIN.40@73.8,54.65 73.85,54.65 74.64,54.65 C_MCU_VDD.1 74.89,55.88 R_MCU_RESET.2 ; v1(75.475,56.9) 75.822,56.988 R_MCU_RESET.2 ; v1(81.652,52.517) 79.338,52.508 78.022,53.305 77.972,53.836 78,54.388 C_MCU_BULK.1 77.488,55.323 R_MCU_RESET.2 ; v1(85.8,47) 85.85,46.95 85.85,46.875 85.91,46.815 R_I2C_SDA.2 86.141,46.631 86.372,46.862 86.603,47.093 86.834,47.324 87.065,47.555 87.421,47.558 87.776,47.561 88.131,47.563 88.487,47.566 88.842,47.569 89.4,47.6 89.676,47.079 89.916,46.832 89.913,46.616 R_I2C_SCL.2 90.177,46.137 90.444,45.873 90.711,45.61 90.977,45.346 91.244,45.083 91.511,44.819 91.778,44.556 92.045,44.292 92.2,43.4 92.042,43.28 92.041,42.942 92.041,42.605 92.018,42.508 R_SENSOR_RESET.2 92.281,42.4 92.652,42.4 93.023,42.4 93.394,42.4 93.765,42.4 94.136,42.4 94.507,42.4 94.877,42.4 95.248,42.4 95.619,42.4 95.99,42.4 96.141,42.248 96.4,41.8 97.2,41.6 97.655,42.24 R_SENSOR_BOOT.2 ; v1(87.649,73.403) 87.649,66.641 C_SENSOR_VDD.1 95.89,58.073 95.89,57.746 95.89,57.419 95.89,57.093 96.046,56.936 96.203,56.78 96.203,56.746 v1(96.252,56.697) ; v1(96.288,54.533) 96.288,54.238 96.288,53.943 96.542,53.689 96.797,53.434 97.051,53.18 97.305,52.926 97.8,52.2 98.812,52.417 99.144,52.417 99.4,52.8 ; v1(98.313,56.46) 98.313,56.122 98.313,55.783 98.313,55.445 98.313,55.106 98.313,54.768 98.562,54.519 98.81,54.27 99.059,54.022 99.059,53.952 v1(99.051,53.944) ; v1(99.483,53.313) U_SENSOR.3@99.8,53.2 ; U_SENSOR.3@99.851,53.124 U_SENSOR.3@99.8,53.2 ; 100.611,51.5 100.6,51.4 100.2,51 99.8,51.2 99.261,51.997 99.01,52.248 99.235,52.475 99.461,52.702 99.4,52.8 ; 100.685,51.5 v1(100.739,50.976) ; v1(101.155,47.05) 101.2,47.005 100.926,46.731 100.652,46.457 100.378,46.182 100.103,45.908 99.829,45.634 99.555,45.36 99.281,45.086 99.007,44.812 98.733,44.537 98.458,44.263 98.184,43.989 97.91,43.715 97.91,43.386 97.91,43.057 97.91,42.729 R_SENSOR_BOOT.2 ; v1(101.478,56.759) 101.5,57.4 102.794,58.4 103.16,58.4 103.525,58.4 C_SENSOR_VDDIO.1 103.89,58.73 104.038,58.879 ; R_SENSOR_CS.2 103.645,42.135 103.2,41.6 101.86,41.87 101.48,41.87 101.1,41.87 100.72,41.87 100.34,41.87 99.96,41.87 99.58,41.87 99.2,41.87 98.82,41.87 98.44,41.87 98.175,42.135 R_SENSOR_BOOT.2 ; v1(104.335,61.578) 104.335,61.896 104.335,62.214 104.591,62.47 104.591,62.494 v1(104.655,62.558) ; 106.336,59.219 106.687,59.219 107.038,59.219 107.389,59.219 107.74,59.219 108.091,59.219 108.364,58.946 108.637,58.673 R_SENSOR_HUB_SCL.2 109.265,58.4 109.62,58.4 109.975,58.4 110.33,58.4 110.685,58.4 111.04,58.4 111.4,59 112.2,59.2 R_SENSOR_HUB_SDA.2 ; 99.4,52.8 U_SENSOR.3@99.8,53.2 ; 99.4,52.8 U_SENSOR.3@99.8,53.2
  Bottom w0.262: 100.632,56.551 100.7,56.5 101.1,56.5
  Bottom w0.275: 101.1,56.5 101.289,56.629 v1(101.478,56.759)
  Bottom w0.3: 100.309,56.553 100.632,56.551
  Bottom w0.4: v1(40.348,64.966) 40.351,54.615 44.2,50.766 v1(44.2,50.6) ; v1(42.889,68.512) 43.839,68.501 43.882,68.458 43.979,68.458 v1(44.072,68.366) ; v1(44.755,68.386) 44.795,68.425 44.795,68.59 45.009,68.805 45.224,69.019 45.438,69.233 45.438,69.513 45.438,69.793 v1(45.438,70.073) ; J_SWD.1 64.86,68.322 75.822,57.361 v1(75.475,56.9) ; v1(81.652,52.517) 81.656,52.513 85.8,48.369 v1(85.8,47) ; J_SENSOR_IO.1 87.51,73.547 87.614,73.443 87.614,73.438 v1(87.649,73.403) ; v1(96.252,56.697) 96.252,56.308 96.252,55.919 96.252,55.53 96.252,55.14 96.252,54.751 96.29,54.714 v1(96.288,54.533) v1(96.288,54.533) ; v1(98.313,56.46) 98.471,56.618 98.634,56.781 98.6,56.8 99.2,56.8 99.371,56.561 99.684,56.558 99.997,56.556 100.309,56.553 ; v1(99.051,53.944) 99.051,53.719 99.234,53.536 99.418,53.352 99.45,53.352 v1(99.483,53.313) ; v1(100.739,50.976) 99.9,50 100.1,48 101.155,47.449 v1(101.155,47.05) ; v1(104.199,59.199) 104.199,59.554 104.199,59.909 104.2,60.264 104.2,60.619 104.2,60.974 104.2,61.329 104.285,61.414 104.285,61.528 v1(104.335,61.578) ; v1(104.655,62.558) 104.919,62.294 105.182,62.031 105.446,61.767 105.71,61.503 105.973,61.24 105.973,60.863 105.973,60.487 105.973,60.11 105.973,59.734 105.973,59.357 105.973,59.225 v1(105.985,59.219)
pads on no net: J_SWD.6 J_SWD.7 J_SWD.8 J_USB.5 J_USB.11 J_USB.NPTH-1 J_USB.NPTH-2 U_LDO.4 U_MAIN.1 U_MAIN.2 U_MAIN.3 U_MAIN.4 U_MAIN.5 U_MAIN.6 U_MAIN.7 U_MAIN.8 U_MAIN.9 U_MAIN.10 U_MAIN.11 U_MAIN.14 U_MAIN.15 U_MAIN.16 U_MAIN.17 U_MAIN.18 U_MAIN.19 U_MAIN.20 U_MAIN.21 U_MAIN.22 U_MAIN.23 U_MAIN.24 U_MAIN.25 U_MAIN.26 U_MAIN.27 U_MAIN.28 U_MAIN.29 U_MAIN.30 U_MAIN.31 U_MAIN.33 U_MAIN.34 U_MAIN.35 U_MAIN.36 U_MAIN.37 U_MAIN.39 U_MAIN.43 U_MAIN.44 U_MAIN.45 U_MAIN.46 U_MAIN.49 U_MAIN.52 U_MAIN.53 U_MAIN.54 U_MAIN.55 U_MAIN.58 U_MAIN.59 U_MAIN.60 U_MAIN.61 U_MAIN.62 U_MAIN.63 U_MAIN.64 U_SENSOR.1 U_SENSOR.7 U_SENSOR.8 U_SENSOR.12 U_SENSOR.13 U_SENSOR.21 U_SENSOR.22 U_SENSOR.23 U_SENSOR.24 U_USB_UART.4
copper on no net:
  other v2: 37.2,54.4

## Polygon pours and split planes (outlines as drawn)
GND on Bottom (solid): 117.1,85.1 25.7,85.1 25.7,25.7 117.1,25.7
GND on Bottom (solid): 65.635,76.594 65.355,76.594 65.39,76.565 65.484,76.452 65.495,76.43 65.506,76.452 65.6,76.565
GND on Bottom (solid): 65.495,75.64 65.484,75.618 65.399,75.515 65.591,75.515 65.506,75.618
GND on Bottom (solid): 65.61,75.496 65.61,75.304 65.713,75.389 65.735,75.4 65.713,75.411
GND on Bottom (solid): 69.305,75.64 69.294,75.618 69.2,75.505 69.087,75.411 69.065,75.4 69.087,75.389 69.2,75.295 69.294,75.182 69.305,75.16 69.316,75.182 69.41,75.295 69.523,75.389 69.545,75.4 69.523,75.411 69.41,75.505 69.316,75.618
GND on Bottom (solid): 68.035,75.64 68.024,75.618 67.93,75.505 67.817,75.411 67.795,75.4 67.817,75.389 67.93,75.295 68.024,75.182 68.035,75.16 68.046,75.182 68.14,75.295 68.253,75.389 68.275,75.4 68.253,75.411 68.14,75.505 68.046,75.618
GND on Bottom (solid): 66.765,75.64 66.754,75.618 66.66,75.505 66.547,75.411 66.525,75.4 66.547,75.389 66.66,75.295 66.754,75.182 66.765,75.16 66.776,75.182 66.87,75.295 66.983,75.389 67.005,75.4 66.983,75.411 66.87,75.505 66.776,75.618
GND on Bottom (solid): 101.653,57.19 101.537,57.19 101.238,57.19 101.262,57.17 101.305,57.118 101.325,57.128 101.4,57.151 101.478,57.159 101.556,57.151 101.631,57.128 101.659,57.113 101.653,57.179 101.654,57.189
GND on Bottom (solid): 99.615,57.19 99.286,57.19 99.353,57.17 99.422,57.133 99.483,57.083 99.524,57.032 99.525,57.033 99.578,56.959 99.635,56.959 99.614,57.029 99.606,57.108 99.614,57.186
GND on Bottom (solid): 102.792,67.349 102.789,67.319 102.767,67.244 102.73,67.175 102.68,67.114 102.672,67.108 102.672,58.239 103.05,57.861 103.127,57.853 103.202,57.831 103.271,57.794 103.332,57.744 103.382,57.683 103.419,57.614 103.441,57.539 103.449,57.461 103.441,57.383 103.419,57.308 103.382,57.239 103.332,57.178 103.272,57.129 103.503,56.898 104.47,56.898 104.524,56.893 104.576,56.877 104.623,56.852 104.665,56.818 105.157,56.326 105.157,60.962 105.127,61.097 104.708,61.437 104.705,61.425 104.681,61.382 104.677,61.336 104.654,61.261 104.617,61.192 104.6,61.171 104.6,60.974 104.6,60.619 104.6,60.264 104.599,59.909 104.599,59.554 104.599,59.199 104.591,59.121 104.569,59.046 104.532,58.977 104.482,58.916 104.421,58.866 104.352,58.83 104.277,58.807 104.199,58.799 104.121,58.807 104.046,58.83 103.977,58.866 103.916,58.916 103.866,58.977 103.83,59.046 103.807,59.121 103.799,59.199 103.799,59.554 103.799,59.909 103.8,60.264 103.8,60.619 103.8,60.974 103.8,61.33 103.808,61.407 103.83,61.482 103.867,61.552 103.89,61.579 103.892,61.606 103.915,61.681 103.952,61.75 104.002,61.81 104.052,61.861 104.113,61.911 104.121,61.915 104.117,61.918 104.083,61.959 104.058,62.007 104.051,62.028 104.05,62.027 103.943,62.358 103.945,62.358 103.935,62.389 103.93,62.442 103.931,62.45 103.93,62.45 104.033,66.108
GND on Bottom (solid): 105.884,53.119 105.884,52.956 105.893,52.945 105.893,53.117
GND on Bottom (solid): 106.572,53.85 106.56,53.838 106.564,53.798 106.556,53.72 106.533,53.645 106.496,53.576 106.447,53.516 106.443,53.512 106.443,51.366 106.486,51.37 106.572,51.456

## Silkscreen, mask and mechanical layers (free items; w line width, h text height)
Top Overlay:
  text "3V3 • SWD • 2L" at 43.4,83.4 h0.48
  text "I2C 0x4A • USB-C UART" at 98.4,83.4 h0.5
  text "MSPM0G3507SPMR + CH340N" at 60.4,29.9 h0.52
  text "BNO085" at 101.4,29.9 h0.55
  text "QUICK CONFIGURE • SENSOR BOARD" at 76.4,27.4 h0.65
